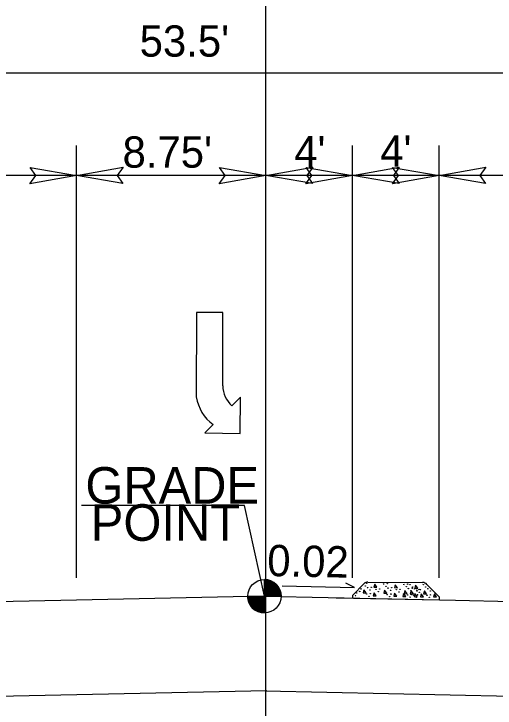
# Model space of a CAD drawing. Extents: x 573813 to 575363, y -54752 to -53123.
# Drawn here: x 574360.94 to 574391.69, y -54415.64 to -54371.3 of the extents above; entities that cross this region are included whole.
import ezdxf

# ---------------------------------------------------------------- set-up
doc = ezdxf.new("R2010")
doc.units = 0
for name, color, linetype in [('Old_Level_1', 7, 'Continuous'), ('Old_Level_11', 7, 'Continuous'), ('Old_Level_2', 7, 'Continuous'), ('Old_Level_3', 7, 'Continuous'), ('Prop Lane Arrow CELL', 7, 'Continuous')]:
    doc.layers.add(name, color=color, linetype=linetype)

msp = doc.modelspace()

# ---------------------------------------------------------------- linework, layer by layer
at = {"layer": 'Old_Level_1'}
for p, q in [((574376.945, -54407.429), (574376.943, -54408.493)), ((574376.943, -54408.493), (574376.945, -54407.429)), ((574378.077, -54407.84), (574382.698, -54407.936)), ((574382.698, -54407.936), (574382.147, -54407.661)), ((574364.941, -54408.742), (574355.041, -54408.948)), ((574376.943, -54408.493), (574364.941, -54408.742)), ((574375.879, -54408.492), (574376.943, -54408.493)), ((574376.943, -54408.493), (574376.943, -54409.556)), ((574378.007, -54408.493), (574376.943, -54408.493)), ((574376.943, -54408.493), (574389.149, -54408.746)), ((574389.149, -54408.746), (574399.149, -54408.954)), ((574377.102, -54414.546), (574357.336, -54414.957)), ((574376.988, -54414.546), (574396.754, -54414.957))]:
    msp.add_line(p, q, dxfattribs=at)
for points in [[(574376.959, -54408.493), (574376.96, -54407.429), (574376.96, -54407.429)], [(574376.981, -54408.493), (574376.981, -54407.429)], [(574377.002, -54408.493), (574377.002, -54407.431)], [(574377.023, -54408.492), (574377.023, -54407.431)], [(574377.045, -54408.492), (574377.045, -54407.434)], [(574377.066, -54408.493), (574377.066, -54407.436)], [(574377.087, -54408.493), (574377.087, -54407.439)], [(574377.108, -54408.493), (574377.109, -54407.443)], [(574377.13, -54408.493), (574377.13, -54407.445)], [(574377.151, -54408.493), (574377.151, -54407.45)], [(574377.172, -54408.493), (574377.172, -54407.455)], [(574377.193, -54408.492), (574377.194, -54407.46)], [(574377.215, -54408.493), (574377.215, -54407.464)], [(574377.236, -54408.493), (574377.236, -54407.472)], [(574377.258, -54408.493), (574377.257, -54407.476)], [(574377.279, -54408.493), (574377.279, -54407.484)], [(574377.3, -54408.493), (574377.3, -54407.491)], [(574377.321, -54408.493), (574377.321, -54407.497)], [(574377.343, -54408.493), (574377.343, -54407.507)], [(574377.363, -54408.493), (574377.364, -54407.516)], [(574377.385, -54408.493), (574377.385, -54407.526)], [(574377.406, -54408.493), (574377.406, -54407.535)], [(574377.428, -54408.493), (574377.427, -54407.545)], [(574377.449, -54408.493), (574377.449, -54407.557)], [(574377.47, -54408.493), (574377.47, -54407.569)], [(574377.491, -54408.493), (574377.491, -54407.58)], [(574377.513, -54408.493), (574377.513, -54407.595)], [(574377.534, -54408.493), (574377.534, -54407.608)], [(574377.555, -54408.493), (574377.555, -54407.623)], [(574377.577, -54408.493), (574377.576, -54407.637)], [(574377.598, -54408.493), (574377.598, -54407.654)], [(574377.619, -54408.493), (574377.619, -54407.67)], [(574377.64, -54408.493), (574377.64, -54407.689)], [(574377.662, -54408.493), (574377.662, -54407.708)], [(574377.683, -54408.493), (574377.683, -54407.727)], [(574377.704, -54408.493), (574377.704, -54407.748)], [(574377.725, -54408.493), (574377.725, -54407.772)], [(574377.747, -54408.493), (574377.747, -54407.795)], [(574377.768, -54408.493), (574377.768, -54407.821)], [(574377.789, -54408.493), (574377.789, -54407.847)], [(574377.81, -54408.493), (574377.811, -54407.876)], [(574377.832, -54408.493), (574377.832, -54407.907)], [(574377.853, -54408.492), (574377.853, -54407.94)], [(574377.874, -54408.493), (574377.874, -54407.977)], [(574377.896, -54408.493), (574377.896, -54408.018)], [(574377.917, -54408.493), (574377.917, -54408.063)], [(574377.938, -54408.493), (574377.938, -54408.112)], [(574377.959, -54408.493), (574377.959, -54408.176)], [(574377.981, -54408.493), (574377.981, -54408.252)], [(574378.002, -54408.493), (574378.002, -54408.377)], [(574375.891, -54408.644), (574375.891, -54408.493)], [(574375.912, -54408.753), (574375.913, -54408.493)], [(574375.934, -54408.826), (574375.934, -54408.493)], [(574375.955, -54408.885), (574375.955, -54408.493)], [(574375.976, -54408.935), (574375.976, -54408.493)], [(574375.998, -54408.98), (574375.998, -54408.493)], [(574376.019, -54409.018), (574376.019, -54408.493)], [(574376.04, -54409.053), (574376.04, -54408.492)], [(574376.061, -54409.086), (574376.061, -54408.493)], [(574376.083, -54409.117), (574376.083, -54408.493)], [(574376.104, -54409.145), (574376.104, -54408.493)], [(574376.125, -54409.171), (574376.125, -54408.493)], [(574376.147, -54409.197), (574376.147, -54408.493)], [(574376.168, -54409.221), (574376.168, -54408.493)], [(574376.189, -54409.242), (574376.189, -54408.493)], [(574376.21, -54409.263), (574376.21, -54408.493)], [(574376.232, -54409.282), (574376.232, -54408.493)], [(574376.253, -54409.301), (574376.253, -54408.493)], [(574376.274, -54409.32), (574376.274, -54408.493)], [(574376.295, -54409.337), (574376.295, -54408.493)], [(574376.317, -54409.351), (574376.317, -54408.493)], [(574376.338, -54409.367), (574376.338, -54408.493)], [(574376.359, -54409.381), (574376.359, -54408.493)], [(574376.381, -54409.396), (574376.381, -54408.492)], [(574376.402, -54409.408), (574376.402, -54408.493)], [(574376.423, -54409.419), (574376.423, -54408.493)], [(574376.444, -54409.431), (574376.444, -54408.493)], [(574376.465, -54409.443), (574376.466, -54408.493)], [(574376.487, -54409.453), (574376.487, -54408.493)], [(574376.508, -54409.462), (574376.508, -54408.493)], [(574376.529, -54409.472), (574376.529, -54408.492)], [(574376.551, -54409.481), (574376.551, -54408.493)], [(574376.572, -54409.49), (574376.572, -54408.493)], [(574376.593, -54409.497), (574376.593, -54408.493)], [(574376.614, -54409.504), (574376.614, -54408.493)], [(574376.636, -54409.512), (574376.636, -54408.493)], [(574376.657, -54409.516), (574376.657, -54408.493)], [(574376.678, -54409.523), (574376.678, -54408.493)], [(574376.7, -54409.528), (574376.699, -54408.493)], [(574376.721, -54409.533), (574376.721, -54408.493)], [(574376.742, -54409.537), (574376.742, -54408.493)], [(574376.763, -54409.542), (574376.763, -54408.493)], [(574376.785, -54409.545), (574376.785, -54408.493)], [(574376.806, -54409.547), (574376.806, -54408.493)], [(574376.827, -54409.549), (574376.827, -54408.493)], [(574376.849, -54409.551), (574376.848, -54408.493)], [(574376.87, -54409.554), (574376.87, -54408.492)], [(574376.891, -54409.554), (574376.891, -54408.493)], [(574376.912, -54409.556), (574376.912, -54408.493)], [(574376.934, -54409.556), (574376.934, -54409.556), (574376.933, -54408.493)]]:
    msp.add_lwpolyline(points, dxfattribs=at)
msp.add_circle((574376.944, -54408.493), 1.064, dxfattribs=at)
for start, end in [(359.9904, 89.9904), (179.9904, 269.9904)]:
    msp.add_arc((574376.944, -54408.493), 1.064, start, end, dxfattribs=at)
at = {"layer": 'Old_Level_11'}
for p, q in [((574409.445, -54375.077), (574344.643, -54375.077)), ((574364.94, -54407.324), (574364.941, -54379.703)), ((574382.578, -54407.325), (574382.578, -54379.703)), ((574388.111, -54407.325), (574388.111, -54379.71)), ((574364.941, -54381.626), (574348.44, -54381.626)), ((574377.045, -54381.626), (574364.941, -54381.626)), ((574382.578, -54381.626), (574377.045, -54381.626)), ((574388.111, -54381.626), (574382.578, -54381.626)), ((574405.749, -54381.626), (574388.111, -54381.626)), ((574375.674, -54402.702), (574365.253, -54402.703)), ((574376.943, -54408.493), (574375.674, -54402.702))]:
    msp.add_line(p, q, dxfattribs=at)
for points in [[(574361.971, -54381.114), (574364.941, -54381.626), (574361.954, -54382.154), (574362.333, -54381.626)], [(574367.911, -54382.137), (574364.941, -54381.626), (574367.927, -54381.098), (574367.548, -54381.626)], [(574374.075, -54381.114), (574377.045, -54381.626), (574374.058, -54382.154), (574374.438, -54381.626)], [(574380.015, -54382.137), (574377.045, -54381.626), (574380.031, -54381.098), (574379.652, -54381.626)], [(574379.608, -54381.114), (574382.578, -54381.626), (574379.592, -54382.154), (574379.971, -54381.626)], [(574385.548, -54382.137), (574382.578, -54381.626), (574385.565, -54381.098), (574385.186, -54381.626)], [(574385.141, -54381.114), (574388.111, -54381.626), (574385.125, -54382.154), (574385.504, -54381.626)], [(574391.081, -54382.137), (574388.111, -54381.626), (574391.098, -54381.098), (574390.719, -54381.626)]]:
    msp.add_lwpolyline(points, close=True, dxfattribs=at)
at = {"layer": 'Old_Level_2'}
msp.add_line((574377.045, -54416.958), (574377.045, -54366.501), dxfattribs=at)
at = {"layer": 'Old_Level_3'}
for p, q in [((574383.313, -54407.686), (574382.576, -54408.441)), ((574383.551, -54407.585), (574387.046, -54407.616)), ((574383.996, -54407.728), (574383.942, -54407.917)), ((574383.942, -54407.917), (574384.14, -54407.924)), ((574384.14, -54407.924), (574383.996, -54407.728)), ((574385.31, -54407.755), (574385.256, -54407.944)), ((574385.256, -54407.944), (574385.453, -54407.951)), ((574385.453, -54407.951), (574385.31, -54407.755)), ((574386.611, -54407.782), (574386.557, -54407.97)), ((574386.557, -54407.97), (574386.754, -54407.978)), ((574386.754, -54407.978), (574386.611, -54407.782)), ((574388.109, -54408.532), (574387.335, -54407.74)), ((574382.576, -54408.441), (574382.578, -54408.61)), ((574383.31, -54408.081), (574383.256, -54408.27)), ((574383.256, -54408.27), (574383.454, -54408.277)), ((574383.454, -54408.277), (574383.31, -54408.081)), ((574383.953, -54408.273), (574383.899, -54408.462)), ((574384.096, -54408.469), (574383.953, -54408.273)), ((574384.624, -54408.108), (574384.57, -54408.297)), ((574384.57, -54408.297), (574384.767, -54408.304)), ((574384.767, -54408.304), (574384.624, -54408.108)), ((574385.266, -54408.3), (574385.212, -54408.489)), ((574385.409, -54408.496), (574385.266, -54408.3)), ((574385.838, -54408.322), (574385.784, -54408.511)), ((574385.981, -54408.518), (574385.838, -54408.322)), ((574385.925, -54408.135), (574385.871, -54408.323)), ((574385.871, -54408.323), (574386.068, -54408.33)), ((574386.068, -54408.33), (574385.925, -54408.135)), ((574386.323, -54408.151), (574386.269, -54408.34)), ((574386.269, -54408.34), (574386.467, -54408.347)), ((574386.467, -54408.347), (574386.323, -54408.151)), ((574386.567, -54408.327), (574386.513, -54408.515)), ((574386.711, -54408.523), (574386.567, -54408.327)), ((574386.965, -54408.343), (574386.911, -54408.532)), ((574387.109, -54408.539), (574386.965, -54408.343)), ((574387.165, -54408.151), (574387.111, -54408.34)), ((574387.111, -54408.34), (574387.309, -54408.347)), ((574387.309, -54408.347), (574387.165, -54408.151)), ((574387.807, -54408.343), (574387.753, -54408.532)), ((574387.951, -54408.539), (574387.807, -54408.343)), ((574381.541, -54408.588), (574388.135, -54408.725)), ((574383.899, -54408.462), (574384.096, -54408.469)), ((574385.212, -54408.489), (574385.409, -54408.496)), ((574385.784, -54408.511), (574385.981, -54408.518)), ((574386.513, -54408.515), (574386.711, -54408.523)), ((574386.911, -54408.532), (574387.109, -54408.539)), ((574387.753, -54408.532), (574387.951, -54408.539)), ((574388.109, -54408.532), (574388.111, -54408.726))]:
    msp.add_line(p, q, dxfattribs=at)
for centre in [(574383.119, -54408.023), (574383.402, -54407.834), (574383.48, -54407.668), (574383.48, -54407.668), (574383.535, -54407.949), (574383.77, -54407.925), (574384.305, -54408.028), (574384.558, -54407.718), (574384.558, -54407.718), (574384.715, -54407.861), (574384.794, -54407.695), (574384.794, -54407.695), (574384.848, -54407.976), (574385.084, -54407.952), (574385.859, -54407.745), (574385.859, -54407.745), (574386.016, -54407.887), (574386.095, -54407.721), (574386.095, -54407.721), (574386.149, -54408.002), (574386.257, -54407.762), (574386.257, -54407.762), (574386.385, -54407.978), (574386.414, -54407.904), (574386.547, -54408.019), (574387.099, -54407.762), (574387.099, -54407.762), (574387.256, -54407.904), (574387.389, -54408.019), (574382.766, -54408.462), (574382.845, -54408.295), (574383.04, -54408.189), (574383.478, -54408.357), (574383.692, -54408.091), (574383.714, -54408.333), (574384.069, -54408.052), (574384.226, -54408.195), (574384.792, -54408.384), (574385.005, -54408.118), (574385.027, -54408.36), (574385.382, -54408.079), (574385.539, -54408.221), (574385.618, -54408.055), (574386.093, -54408.41), (574386.306, -54408.145), (574386.328, -54408.386), (574386.491, -54408.427), (574386.683, -54408.106), (574386.704, -54408.161), (574386.727, -54408.403), (574386.829, -54408.062), (574386.84, -54408.248), (574386.919, -54408.082), (574387.333, -54408.427), (574387.547, -54408.161), (574387.569, -54408.403), (574383.636, -54408.499), (574384.949, -54408.526), (574386.25, -54408.553), (574386.648, -54408.569), (574387.49, -54408.569)]:
    msp.add_circle(centre, 0.0132, dxfattribs=at)
for centre, radius, start, end in [((574383.555, -54407.923), 0.338, 90.6677, 135.6677), ((574387.04, -54408.028), 0.412, 44.3331, 89.1598), ((574387.04, -54408.028), 0.412, 44.3331, 89.1598)]:
    msp.add_arc(centre, radius, start, end, dxfattribs=at)
at = {"layer": 'Prop Lane Arrow CELL'}
for p, q in [((574372.605, -54390.366), (574372.597, -54395.764)), ((574374.294, -54390.366), (574372.605, -54390.366)), ((574374.285, -54395.052), (574374.294, -54390.366)), ((574375.419, -54395.789), (574374.876, -54396.33)), ((574375.394, -54398.091), (574375.419, -54395.789)), ((574373.673, -54397.532), (574373.143, -54398.066)), ((574373.143, -54398.066), (574375.394, -54398.091))]:
    msp.add_line(p, q, dxfattribs=at)
for centre, radius, start, end in [((574375.961, -54395.052), 1.676, 180, 229.6582), ((574375.253, -54395.358), 2.687, 188.6761, 233.9878)]:
    msp.add_arc(centre, radius, start, end, dxfattribs=at)

# ---------------------------------------------------------------- texts
at = {"layer": 'Old_Level_1'}
msp.add_text('0.02', height=2, rotation=358.8082, dxfattribs=at).set_placement((574377.113, -54407.202))
at = {"layer": 'Old_Level_11'}
for s, p in [("53.5'", (574368.976, -54374.031)), ("8.75'", (574367.884, -54381.124)), ("4'", (574378.851, -54381.095)), ("4'", (574384.346, -54381.054))]:
    msp.add_text(s, height=2, rotation=359.9999, dxfattribs=at).set_placement(p)
at = {"layer": 'Old_Level_3'}
for s, p in [('GRADE', (574365.508, -54402.58)), ('POINT', (574365.856, -54404.952))]:
    msp.add_text(s, height=2.3333, rotation=360, dxfattribs=at).set_placement(p)

doc.saveas('drawing.dxf')
